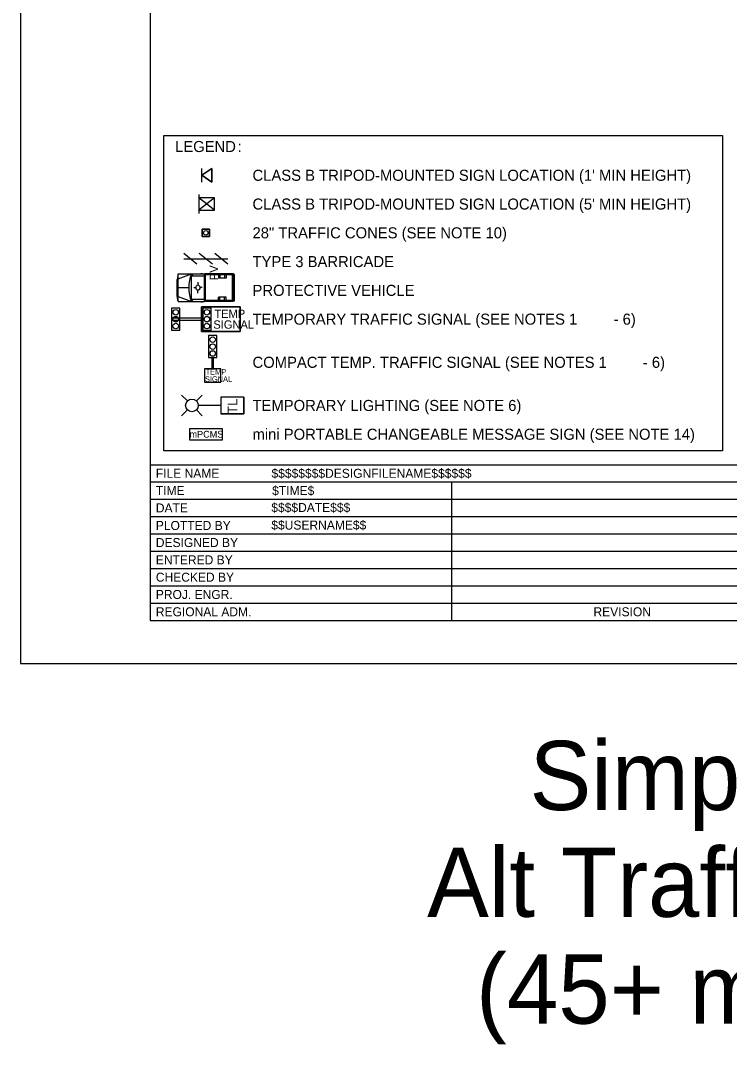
# Model space of a CAD drawing. Extents: x 99979.8 to 100075.7, y 99995 to 100010.7.
# Drawn here: x 99999.06 to 100004.19, y 99996.93 to 100004.34 of the extents above; entities that cross this region are included whole.
import ezdxf

# ---------------------------------------------------------------- set-up
doc = ezdxf.new("R2010")
doc.units = 0
for name, color, linetype in [('SH_GI_PlotLimits', 7, 'Continuous'), ('SH_GI_SheetBorder', 7, 'Continuous'), ('SH_GI_SheetLocationText', 7, 'Continuous'), ('SH_GI_SheetTextInCells', 7, 'Continuous'), ('SH_GI_TitleBlockText', 7, 'Continuous'), ('TR_WZ_BarricadeType3', 7, 'Continuous'), ('TR_WZ_PortableChangeMessageSign', 7, 'Continuous'), ('TR_WZ_PortableLightStandard', 7, 'Continuous'), ('TR_WZ_PortableSignMount5ftMinBlk-Wht', 7, 'Continuous'), ('TR_WZ_PortableSignMountBlk-Wht', 7, 'Continuous'), ('TR_WZ_ProtectiveVehicle', 7, 'Continuous'), ('TR_WZ_TempSignal', 7, 'Continuous'), ('TR_WZ_TrafficCone', 7, 'Continuous'), ('TR_WZ_WorkZoneDetails', 7, 'Continuous'), ('TR_WZ_WorkZoneTextCurrent', 7, 'Continuous')]:
    doc.layers.add(name, color=color, linetype=linetype)

msp = doc.modelspace()

# ---------------------------------------------------------------- linework, layer by layer
at = {"layer": 'SH_GI_PlotLimits'}
msp.add_lwpolyline([(99999.0625, 99999.6875), (100016.0625, 99999.6875), (100016.0625, 100010.6875), (99999.0625, 100010.6875)], close=True, dxfattribs=at)
at = {"layer": 'SH_GI_SheetBorder'}
for p, q in [((100000, 100010.375), (100000, 100000)), ((100000, 100001.1259), (100015.75, 100001.1259)), ((100000, 100001.0008), (100007.4566, 100001.0008)), ((100002.179, 100001.0008), (100002.179, 100000)), ((100000, 100000.8757), (100002.1821, 100000.8757)), ((100002.1821, 100000.8757), (100005.4466, 100000.8757)), ((100000, 100000.7506), (100002.1821, 100000.7506)), ((100002.1821, 100000.7506), (100005.4466, 100000.7506)), ((100000, 100000.6255), (100005.4466, 100000.6255)), ((100000, 100000.5004), (100005.4466, 100000.5004)), ((100000, 100000.3753), (100005.4466, 100000.3753)), ((100000, 100000.2502), (100005.4466, 100000.2502)), ((100000, 100000.1251), (100005.4466, 100000.1251)), ((100000, 100000), (100015.75, 100000))]:
    msp.add_line(p, q, dxfattribs=at)
at = {"layer": 'TR_WZ_BarricadeType3'}
for p, q in [((100000.3381, 100002.5743), (100000.2425, 100002.6535)), ((100000.4503, 100002.5743), (100000.3547, 100002.6535)), ((100000.5625, 100002.5743), (100000.4669, 100002.6535)), ((100000.2425, 100002.6139), (100000.5625, 100002.6139))]:
    msp.add_line(p, q, dxfattribs=at)
at = {"layer": 'TR_WZ_PortableChangeMessageSign'}
msp.add_lwpolyline([(100000.2841, 100001.3059), (100000.5241, 100001.3059), (100000.5241, 100001.3859), (100000.2841, 100001.3859)], close=True, dxfattribs=at)
msp.add_lwpolyline([(100000.2841, 100001.3059), (100000.5241, 100001.3059), (100000.5241, 100001.3859), (100000.2841, 100001.3859), (100000.2841, 100001.3059)], dxfattribs=at)
at = {"layer": 'TR_WZ_PortableLightStandard'}
for p, q in [((100000.2692, 100001.5863), (100000.2261, 100001.6293)), ((100000.3339, 100001.5863), (100000.377, 100001.6293)), ((100000.6777, 100001.6139), (100000.5117, 100001.6139)), ((100000.5117, 100001.6139), (100000.5117, 100001.4939)), ((100000.6777, 100001.6139), (100000.5117, 100001.6139)), ((100000.6777, 100001.6139), (100000.6777, 100001.4939)), ((100000.2692, 100001.5215), (100000.2261, 100001.4784)), ((100000.3339, 100001.5215), (100000.377, 100001.4784)), ((100000.5117, 100001.5539), (100000.3473, 100001.5539)), ((100000.6777, 100001.4939), (100000.5117, 100001.4939)), ((100000.5117, 100001.4939), (100000.6777, 100001.4939))]:
    msp.add_line(p, q, dxfattribs=at)
for points in [[(100000.5117, 100001.6139), (100000.5117, 100001.5539), (100000.5117, 100001.4939)], [(100000.6777, 100001.4939), (100000.6777, 100001.5539), (100000.6777, 100001.6139)]]:
    msp.add_lwpolyline(points, dxfattribs=at)
msp.add_circle((100000.3015, 100001.5539), 0.0457, dxfattribs=at)
msp.add_circle((100000.3015, 100001.5539), 0.0457, dxfattribs=at)
at = {"layer": 'TR_WZ_PortableSignMount5ftMinBlk-Wht'}
for p, q in [((100000.3512, 100003.0789), (100000.3512, 100002.9409)), ((100000.4663, 100002.9651), (100000.3512, 100003.0547)), ((100000.4663, 100003.0547), (100000.3512, 100002.9651)), ((100000.4088, 100003.0099), (100000.4088, 100003.0099)), ((100000.4089, 100003.0098), (100000.4089, 100003.0098))]:
    msp.add_line(p, q, dxfattribs=at)
msp.add_lwpolyline([(100000.4663, 100002.9651), (100000.4663, 100003.0547), (100000.3512, 100003.0547), (100000.3512, 100002.9651)], close=True, dxfattribs=at)
at = {"layer": 'TR_WZ_PortableSignMountBlk-Wht'}
msp.add_line((100000.3728, 100003.1679), (100000.3728, 100003.2679), dxfattribs=at)
msp.add_lwpolyline([(100000.3728, 100003.2178), (100000.4447, 100003.2679), (100000.4447, 100003.1679)], close=True, dxfattribs=at)
at = {"layer": 'TR_WZ_ProtectiveVehicle'}
for p, q in [((100000.2036, 100002.5059), (100000.1944, 100002.4655)), ((100000.2036, 100002.3059), (100000.2036, 100002.5059)), ((100000.2036, 100002.5059), (100000.3925, 100002.5059)), ((100000.2036, 100002.4693), (100000.2981, 100002.5059)), ((100000.2981, 100002.3059), (100000.2981, 100002.5059)), ((100000.2998, 100002.3059), (100000.2998, 100002.5059)), ((100000.3098, 100002.4904), (100000.2998, 100002.5059)), ((100000.2998, 100002.4904), (100000.3925, 100002.4904)), ((100000.3668, 100002.5087), (100000.3781, 100002.5087)), ((100000.3925, 100002.3059), (100000.3925, 100002.5059)), ((100000.601, 100002.5059), (100000.3953, 100002.5059)), ((100000.3953, 100002.3059), (100000.3953, 100002.5059)), ((100000.5952, 100002.4979), (100000.4011, 100002.4979)), ((100000.4011, 100002.3139), (100000.4011, 100002.4979)), ((100000.4938, 100002.4979), (100000.4938, 100002.4749)), ((100000.5488, 100002.4749), (100000.4938, 100002.4749)), ((100000.5038, 100002.4979), (100000.5038, 100002.4749)), ((100000.5378, 100002.4979), (100000.5378, 100002.4749)), ((100000.5488, 100002.4979), (100000.5488, 100002.4749)), ((100000.5952, 100002.3139), (100000.5952, 100002.4979)), ((100000.601, 100002.3059), (100000.601, 100002.5059)), ((100000.6061, 100002.5026), (100000.6017, 100002.5026)), ((100000.6017, 100002.3092), (100000.6017, 100002.5026)), ((100000.6106, 100002.3153), (100000.6106, 100002.4965)), ((100000.1944, 100002.3463), (100000.1944, 100002.4655)), ((100000.2036, 100002.4059), (100000.2795, 100002.4059)), ((100000.315, 100002.4058), (100000.3276, 100002.4058)), ((100000.3458, 100002.4444), (100000.3455, 100002.4293)), ((100000.3592, 100002.4062), (100000.3592, 100002.4062)), ((100000.376, 100002.4067), (100000.3611, 100002.4063)), ((100000.6106, 100002.42), (100000.6017, 100002.4162)), ((100000.6082, 100002.4059), (100000.6041, 100002.4059)), ((100000.6061, 100002.4031), (100000.6061, 100002.4087)), ((100000.2036, 100002.3059), (100000.1944, 100002.3463)), ((100000.2036, 100002.3425), (100000.2981, 100002.3059)), ((100000.3451, 100002.3663), (100000.3451, 100002.3824)), ((100000.5488, 100002.3369), (100000.4938, 100002.3369)), ((100000.4938, 100002.3139), (100000.4938, 100002.3369)), ((100000.5038, 100002.3139), (100000.5038, 100002.3369)), ((100000.5378, 100002.3139), (100000.5378, 100002.3369)), ((100000.5488, 100002.3139), (100000.5488, 100002.3369)), ((100000.6106, 100002.3918), (100000.6017, 100002.3956)), ((100000.2036, 100002.3059), (100000.3925, 100002.3059)), ((100000.2998, 100002.3059), (100000.3118, 100002.3214)), ((100000.2998, 100002.3214), (100000.3925, 100002.3214)), ((100000.3668, 100002.3031), (100000.3781, 100002.3031)), ((100000.601, 100002.3059), (100000.3953, 100002.3059)), ((100000.5952, 100002.3139), (100000.4011, 100002.3139)), ((100000.6061, 100002.3092), (100000.6017, 100002.3092))]:
    msp.add_line(p, q, dxfattribs=at)
for centre, major_axis, start_param, end_param in [((100000.4331, 100002.4059), (0, -0.2099), 4.215852, 5.209111), ((100000.6061, 100002.4965), (0, 0.0061), 4.712389, 6.283185), ((100000.6061, 100002.3153), (0, -0.0061), 6.283185, 7.853982)]:
    msp.add_ellipse(centre, major_axis=major_axis, ratio=0.73155, start_param=start_param, end_param=end_param, dxfattribs=at)
for centre, major_axis in [((100000.3451, 100002.4059), (0, 0.0193)), ((100000.6061, 100002.4059), (0, 0.00282))]:
    msp.add_ellipse(centre, major_axis=major_axis, ratio=0.73155, dxfattribs=at)
at = {"layer": 'TR_WZ_TempSignal'}
for p, q in [((100000.215, 100002.2578), (100000.1551, 100002.2578)), ((100000.1551, 100002.2578), (100000.1551, 100002.098)), ((100000.215, 100002.098), (100000.215, 100002.2578)), ((100000.3701, 100002.2679), (100000.6501, 100002.2679)), ((100000.3701, 100002.0879), (100000.3701, 100002.2679)), ((100000.6501, 100002.2679), (100000.3701, 100002.2679)), ((100000.3701, 100002.2679), (100000.3701, 100002.1846)), ((100000.44, 100002.2578), (100000.3801, 100002.2578)), ((100000.3801, 100002.2578), (100000.3801, 100002.098)), ((100000.44, 100002.098), (100000.44, 100002.2578)), ((100000.6501, 100002.2679), (100000.6501, 100002.0879)), ((100000.6501, 100002.0879), (100000.6501, 100002.2679)), ((100000.3701, 100002.1846), (100000.1551, 100002.1846)), ((100000.1551, 100002.1846), (100000.1551, 100002.1712)), ((100000.3701, 100002.1712), (100000.3701, 100002.1846)), ((100000.3701, 100002.1846), (100000.3701, 100002.1712)), ((100000.1551, 100002.1712), (100000.3701, 100002.1712)), ((100000.3701, 100002.1712), (100000.3701, 100002.0879)), ((100000.1551, 100002.098), (100000.215, 100002.098)), ((100000.6501, 100002.0879), (100000.3701, 100002.0879)), ((100000.3701, 100002.0879), (100000.6501, 100002.0879)), ((100000.3801, 100002.098), (100000.44, 100002.098)), ((100000.4819, 100002.0592), (100000.422, 100002.0592)), ((100000.422, 100002.0592), (100000.422, 100001.8995)), ((100000.4819, 100001.8995), (100000.4819, 100002.0592)), ((100000.422, 100001.8995), (100000.4819, 100001.8995)), ((100000.5119, 100001.8195), (100000.3919, 100001.8195)), ((100000.3919, 100001.8195), (100000.3919, 100001.775)), ((100000.5119, 100001.7217), (100000.5119, 100001.8195)), ((100000.3919, 100001.775), (100000.3919, 100001.7662)), ((100000.3919, 100001.7662), (100000.3919, 100001.7217)), ((100000.3919, 100001.7217), (100000.5119, 100001.7217))]:
    msp.add_line(p, q, dxfattribs=at)
for points in [[(100000.215, 100002.2578), (100000.1551, 100002.2578), (100000.1551, 100002.098), (100000.215, 100002.098), (100000.215, 100002.2578)], [(100000.44, 100002.2578), (100000.3801, 100002.2578), (100000.3801, 100002.098), (100000.44, 100002.098), (100000.44, 100002.2578)], [(100000.4819, 100002.0592), (100000.422, 100002.0592), (100000.422, 100001.8995), (100000.4819, 100001.8995), (100000.4819, 100002.0592)], [(100000.5119, 100001.8195), (100000.3919, 100001.8195), (100000.3919, 100001.7217), (100000.5119, 100001.7217), (100000.5119, 100001.8195)]]:
    msp.add_lwpolyline(points, dxfattribs=at)
msp.add_lwpolyline([(100000.4494, 100001.8995), (100000.4544, 100001.8995), (100000.4544, 100001.8195), (100000.4494, 100001.8195)], close=True, dxfattribs=at)
for centre in [(100000.1851, 100002.2278), (100000.1851, 100002.2278), (100000.1851, 100002.1779), (100000.1851, 100002.1779), (100000.4101, 100002.2278), (100000.4101, 100002.2278), (100000.4101, 100002.1779), (100000.4101, 100002.1779), (100000.1851, 100002.128), (100000.1851, 100002.128), (100000.4101, 100002.128), (100000.4101, 100002.128), (100000.4519, 100002.0293), (100000.4519, 100002.0293), (100000.4519, 100001.9794), (100000.4519, 100001.9794), (100000.4519, 100001.9294), (100000.4519, 100001.9294)]:
    msp.add_circle(centre, 0.02, dxfattribs=at)
at = {"layer": 'TR_WZ_TrafficCone'}
for points in [[(100000.3759, 100002.8286), (100000.4293, 100002.8286), (100000.4293, 100002.7752), (100000.3759, 100002.7752), (100000.3759, 100002.8286)], [(100000.3759, 100002.7752), (100000.4293, 100002.7752), (100000.4293, 100002.8286), (100000.3759, 100002.8286), (100000.3759, 100002.7752)]]:
    msp.add_lwpolyline(points, dxfattribs=at)
msp.add_circle((100000.4026, 100002.8019), 0.0167, dxfattribs=at)
at = {"layer": 'TR_WZ_WorkZoneDetails'}
msp.add_lwpolyline([(100000.4447, 100003.1679), (100000.4447, 100003.2679), (100000.3728, 100003.2178), (100000.4447, 100003.1679)], dxfattribs=at)
at = {"layer": 'TR_WZ_WorkZoneTextCurrent'}
msp.add_lwpolyline([(100000.1, 100003.5059), (100004.1384, 100003.5059), (100004.1384, 100001.2259), (100000.1, 100001.2259)], close=True, dxfattribs=at)

# ---------------------------------------------------------------- texts
at = {"layer": 'SH_GI_SheetLocationText'}
for s, p in [('Simple', (100002.743, 99998.6291)), ('Alt Traffic w/ Channelization Devices', (100002.0024, 99997.8571)), ('(45+ mph) Short-Duration Version', (100002.356, 99997.0851))]:
    msp.add_text(s, height=0.5, dxfattribs=at).set_placement(p)
at = {"layer": 'SH_GI_SheetTextInCells'}
for s, height, p in [('FILE NAME', 0.06505, (100000.041, 100001.0308)), ('TIME', 0.06505, (100000.041, 100000.9057)), ('DATE', 0.06505, (100000.041, 100000.7806)), ('PLOTTED BY', 0.06505, (100000.041, 100000.6538)), ('DESIGNED BY', 0.065052, (100000.041, 100000.5304)), ('ENTERED BY', 0.06505, (100000.041, 100000.4053)), ('CHECKED BY', 0.06505, (100000.041, 100000.2802)), ('PROJ. ENGR.', 0.065052, (100000.041, 100000.1551)), ('REGIONAL ADM.', 0.065052, (100000.041, 100000.03)), ('REVISION', 0.06505, (100003.2048, 100000.03))]:
    msp.add_text(s, height=height, dxfattribs=at).set_placement(p)
at = {"layer": 'SH_GI_TitleBlockText'}
for s, height, p in [('$$$$$$$$DESIGNFILENAME$$$$$$', 0.065052, (100000.8775, 100001.0308)), ('$TIME$', 0.06505, (100000.882, 100000.9059)), ('$$$$DATE$$$', 0.065052, (100000.8759, 100000.7835)), ('$$USERNAME$$', 0.065052, (100000.8759, 100000.6567))]:
    msp.add_text(s, height=height, dxfattribs=at).set_placement(p)
at = {"layer": 'TR_WZ_PortableChangeMessageSign'}
msp.add_text('mPCMS', height=0.04909, rotation=360, dxfattribs=at).set_placement((100000.2845, 100001.3214))
at = {"layer": 'TR_WZ_PortableLightStandard'}
msp.add_text('TL', height=0.07, rotation=90, dxfattribs=at).set_placement((100000.6297, 100001.4937))
at = {"layer": 'TR_WZ_ProtectiveVehicle'}
msp.add_text('PV', height=0.06, rotation=90, dxfattribs=at).set_placement((100000.4913, 100002.4597))
at = {"layer": 'TR_WZ_TempSignal'}
for s, height, p in [('TEMP', 0.06, (100000.4641, 100002.1869)), ('SIGNAL', 0.06, (100000.4567, 100002.1089)), ('TEMP', 0.04, (100000.4013, 100001.7766)), ('SIGNAL', 0.04, (100000.3963, 100001.7246))]:
    msp.add_text(s, height=height, dxfattribs=at).set_placement(p)
at = {"layer": 'TR_WZ_WorkZoneTextCurrent'}
for s, p in [('LEGEND', (100000.18, 100003.3859)), (':', (100000.6328, 100003.3859)), ("CLASS B TRIPOD-MOUNTED SIGN LOCATION (1' MIN HEIGHT)", (100000.74, 100003.1779)), ("CLASS B TRIPOD-MOUNTED SIGN LOCATION (5' MIN HEIGHT)", (100000.74, 100002.9699)), ('28" TRAFFIC CONES (SEE NOTE 10)', (100000.74, 100002.7619)), ('TYPE 3 BARRICADE', (100000.74, 100002.5539)), ('PROTECTIVE VEHICLE', (100000.74, 100002.3459)), ('TEMPORARY TRAFFIC SIGNAL (SEE NOTES 1', (100000.74, 100002.1379)), ('- 6)', (100003.3504, 100002.1379)), ('COMPACT TEMP. TRAFFIC SIGNAL (SEE NOTES 1', (100000.74, 100001.8259)), ('- 6)', (100003.5616, 100001.8259)), ('TEMPORARY LIGHTING (SEE NOTE 6)', (100000.74, 100001.5139)), ('mini PORTABLE CHANGEABLE MESSAGE SIGN (SEE NOTE 14)', (100000.74, 100001.3059))]:
    msp.add_text(s, height=0.08, rotation=360, dxfattribs=at).set_placement(p)

doc.saveas('drawing.dxf')
